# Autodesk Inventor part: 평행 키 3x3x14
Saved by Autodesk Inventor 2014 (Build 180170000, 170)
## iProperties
Created: 2026-06
Part Number: 평행 키 3x3x14
Material: 강철, 연강
Document SubType Name: Modeling
Designer: dg
Density: 7.86 g/cm^3
Appearance: 강철
Mass: 0.929637 g
Surface Area: 1.65045 cm^2
Volume: 0.118274 cm^3
Author: jhkim
Description: 키 및 해당 키홈
Creation Date: 2026-05-29
Sending System: Autodesk Inventor 2027
Preprocessor: ST-DEVELOPER v20.1
Author: dg
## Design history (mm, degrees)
node "평행 키 3x3x141"
body "Solid1"
node "기준1"
